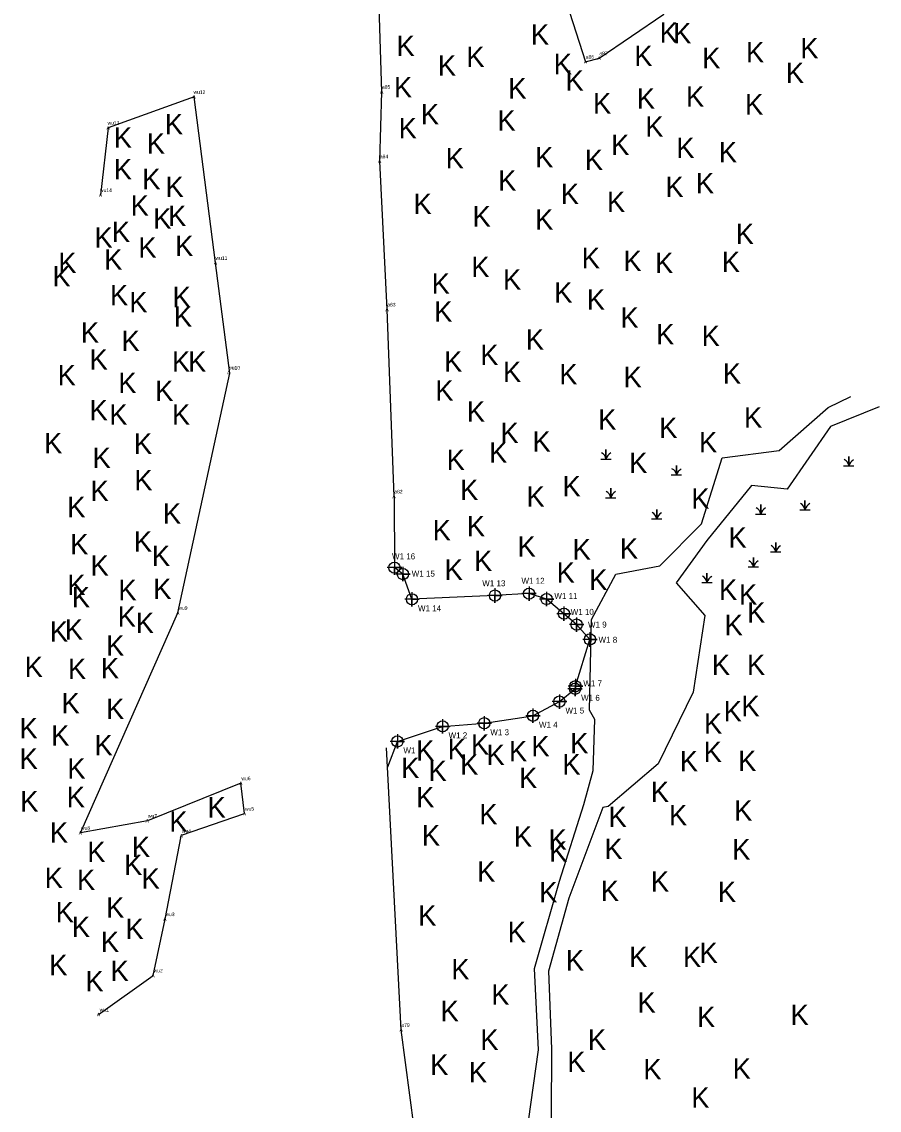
# Model space of a CAD drawing. Extents: x 2028512 to 2029541, y 737100 to 738747.
# Drawn here: x 2028728.5 to 2029086.2, y 737567.9 to 738021.9 of the extents above; entities that cross this region are included whole.
import ezdxf

# ---------------------------------------------------------------- set-up
doc = ezdxf.new("R2010")
doc.units = 0
for name, color, linetype in [('Exist Hydro Jurisdictional Stream or Body of Water NEU Mitigable', 7, 'Continuous'), ('Exist Hydro Swamp or Marsh', 7, 'Continuous'), ('Old_Level_10', 7, 'Continuous'), ('Old_Level_20', 7, 'Continuous'), ('Old_Level_52', 7, 'Continuous'), ('Old_Level_55', 7, 'Continuous'), ('Old_Level_61', 7, 'Continuous')]:
    doc.layers.add(name, color=color, linetype=linetype)

msp = doc.modelspace()

# ---------------------------------------------------------------- linework, layer by layer
at = {"layer": 'Exist Hydro Jurisdictional Stream or Body of Water NEU Mitigable'}
for points in [[(2028936, 737517.23), (2028942.42, 737539.85), (2028939.91, 737563.38), (2028944.05, 737593.1), (2028942.37, 737627.04), (2028952.81, 737663.43), (2028963.03, 737695.43), (2028966.79, 737709.62), (2028967.55, 737730.9), (2028965.32, 737734.83), (2028966.1, 737772.62), (2028976.38, 737791.55), (2028994.69, 737794.94), (2029012.11, 737812.51), (2029020.64, 737839.95), (2029044.47, 737843.01), (2029064.89, 737861), (2029074.27, 737865.65)], [(2029086.17, 737861.26), (2029065.82, 737853.05), (2029047.81, 737826.9), (2029032.96, 737828.41), (2029014.3, 737805.56), (2029001.47, 737787.92), (2029013.48, 737774.19), (2029008.57, 737742.32), (2028993.96, 737712.46), (2028973.16, 737694.62), (2028970.92, 737694.24), (2028956.66, 737656.32), (2028948.19, 737625.98), (2028949.49, 737593.57), (2028949.29, 737565.55), (2028947.28, 737538.25), (2028941.59, 737516.37), (2028941.83, 737507.52)]]:
    msp.add_lwpolyline(points, dxfattribs=at)
at = {"layer": 'Exist Hydro Swamp or Marsh'}
for p, q in [((2028972.2, 737841.29), (2028972.2, 737841.29)), ((2029073.47, 737838.42), (2029073.47, 737838.42)), ((2029001.59, 737834.65), (2029001.59, 737834.65)), ((2028974.17, 737825.15), (2028974.17, 737825.15)), ((2028993.35, 737816.36), (2028993.35, 737816.36)), ((2029036.73, 737818.34), (2029036.73, 737818.34)), ((2029055.19, 737820.13), (2029055.19, 737820.13)), ((2029043, 737802.55), (2029043, 737802.55)), ((2029033.68, 737796.28), (2029033.68, 737796.28)), ((2029014.32, 737789.82), (2029014.32, 737789.82))]:
    msp.add_line(p, q, dxfattribs=at)
for points in [[(2028970.05, 737839.51), (2028972.2, 737839.51), (2028972.2, 737843.45), (2028972.2, 737839.51), (2028974.35, 737839.51)], [(2029071.32, 737836.64), (2029073.47, 737836.64), (2029073.47, 737840.58), (2029073.47, 737836.64), (2029075.62, 737836.64)], [(2028999.44, 737832.87), (2029001.6, 737832.87), (2029001.6, 737836.82), (2029001.6, 737832.87), (2029003.75, 737832.87)], [(2028972.02, 737823.37), (2028974.17, 737823.37), (2028974.17, 737827.31), (2028974.17, 737823.37), (2028976.32, 737823.37)], [(2029034.58, 737816.55), (2029036.73, 737816.55), (2029036.73, 737820.5), (2029036.73, 737816.55), (2029038.88, 737816.55)], [(2029053.04, 737818.35), (2029055.19, 737818.35), (2029055.19, 737822.29), (2029055.19, 737818.35), (2029057.34, 737818.35)], [(2028991.2, 737814.58), (2028993.35, 737814.58), (2028993.35, 737818.53), (2028993.35, 737814.58), (2028995.5, 737814.58)], [(2029040.85, 737800.77), (2029043, 737800.77), (2029043, 737804.72), (2029043, 737800.77), (2029045.15, 737800.77)], [(2029031.53, 737794.49), (2029033.68, 737794.49), (2029033.68, 737798.44), (2029033.68, 737794.49), (2029035.83, 737794.49)], [(2029012.17, 737788.04), (2029014.32, 737788.04), (2029014.32, 737791.98), (2029014.32, 737788.04), (2029016.47, 737788.04)]]:
    msp.add_lwpolyline(points, dxfattribs=at)
for centre, radius, start, end in [((2028969.13, 737839.28), 3.07, 4.1403, 67.535), ((2028976.76, 737837.99), 4.81, 122.1274, 161.6222), ((2029070.41, 737836.42), 3.07, 4.1403, 67.535), ((2029078.03, 737835.12), 4.81, 122.1274, 161.6222), ((2028998.53, 737832.65), 3.07, 4.1403, 67.535), ((2029006.16, 737831.36), 4.81, 122.1274, 161.6222), ((2028971.1, 737823.15), 3.07, 4.1403, 67.535), ((2028978.73, 737821.85), 4.81, 122.1274, 161.6222), ((2029052.12, 737818.12), 3.07, 4.1403, 67.535), ((2029059.75, 737816.83), 4.81, 122.1274, 161.6222), ((2028990.28, 737814.36), 3.07, 4.1403, 67.535), ((2028997.91, 737813.06), 4.81, 122.1274, 161.6222), ((2029033.66, 737816.33), 3.07, 4.1403, 67.535), ((2029041.29, 737815.04), 4.81, 122.1274, 161.6222), ((2029039.93, 737800.55), 3.07, 4.1403, 67.535), ((2029047.56, 737799.26), 4.81, 122.1274, 161.6222), ((2029030.61, 737794.27), 3.07, 4.1403, 67.535), ((2029038.24, 737792.98), 4.81, 122.1274, 161.6222), ((2029011.26, 737787.82), 3.07, 4.1403, 67.535), ((2029018.88, 737786.52), 4.81, 122.1274, 161.6222)]:
    msp.add_arc(centre, radius, start, end, dxfattribs=at)
at = {"layer": 'Old_Level_20'}
for points in [[(2028883.99, 737797.22), (2028883.99, 737791.22), (2028883.99, 737794.22), (2028886.99, 737794.22), (2028880.99, 737794.22)], [(2028887.5, 737794.52), (2028887.5, 737788.52), (2028887.5, 737791.52), (2028890.5, 737791.52), (2028884.5, 737791.52)], [(2028891.28, 737784.02), (2028891.28, 737778.02), (2028891.28, 737781.02), (2028894.28, 737781.02), (2028888.28, 737781.02)], [(2028925.89, 737785.59), (2028925.89, 737779.59), (2028925.89, 737782.59), (2028928.89, 737782.59), (2028922.89, 737782.59)], [(2028940.12, 737786.37), (2028940.12, 737780.37), (2028940.12, 737783.37), (2028943.12, 737783.37), (2028937.12, 737783.37)], [(2028947.42, 737784.12), (2028947.42, 737778.12), (2028947.42, 737781.12), (2028950.42, 737781.12), (2028944.42, 737781.12)], [(2028954.66, 737778.02), (2028954.66, 737772.02), (2028954.66, 737775.02), (2028957.66, 737775.02), (2028951.66, 737775.02)], [(2028959.93, 737773.49), (2028959.93, 737767.49), (2028959.93, 737770.49), (2028962.93, 737770.49), (2028956.93, 737770.49)], [(2028965.52, 737767.25), (2028965.52, 737761.25), (2028965.52, 737764.25), (2028968.52, 737764.25), (2028962.52, 737764.25)], [(2028959.48, 737747.78), (2028959.48, 737741.78), (2028959.48, 737744.78), (2028962.48, 737744.78), (2028956.48, 737744.78)], [(2028959.33, 737746.68), (2028959.33, 737740.68), (2028959.33, 737743.68), (2028962.33, 737743.68), (2028956.33, 737743.68)], [(2028952.81, 737741.37), (2028952.81, 737735.37), (2028952.81, 737738.37), (2028955.81, 737738.37), (2028949.81, 737738.37)], [(2028941.75, 737735.44), (2028941.75, 737729.44), (2028941.75, 737732.44), (2028944.75, 737732.44), (2028938.75, 737732.44)], [(2028904.05, 737731.02), (2028904.05, 737725.02), (2028904.05, 737728.02), (2028907.05, 737728.02), (2028901.05, 737728.02)], [(2028921.45, 737732.32), (2028921.45, 737726.32), (2028921.45, 737729.32), (2028924.45, 737729.32), (2028918.45, 737729.32)], [(2028885.21, 737724.73), (2028885.21, 737718.73), (2028885.21, 737721.73), (2028888.21, 737721.73), (2028882.21, 737721.73)]]:
    msp.add_lwpolyline(points, dxfattribs=at)
for centre in [(2028883.99, 737794.22), (2028887.5, 737791.52), (2028925.89, 737782.59), (2028940.12, 737783.37), (2028891.28, 737781.02), (2028947.42, 737781.12), (2028954.66, 737775.02), (2028959.93, 737770.49), (2028965.52, 737764.25), (2028959.33, 737743.68), (2028959.48, 737744.78), (2028952.81, 737738.37), (2028941.75, 737732.44), (2028904.05, 737728.02), (2028921.45, 737729.32), (2028885.21, 737721.73)]:
    msp.add_circle(centre, 2.34, dxfattribs=at)
at = {"layer": 'Old_Level_52'}
for points in [[(2028878.7, 737992.71), (2028876.87, 738050.54), (2028924.08, 738056.04), (2028953.04, 738038.2), (2028963.71, 738005.21), (2028969.41, 738006.68), (2028996.29, 738025.08), (2028999.97, 738052.31), (2028981.59, 738072.49), (2028952.85, 738139.55), (2028963.08, 738144.58), (2028949.25, 738167.62)], [(2028883.86, 737823.92), (2028880.93, 737901.91), (2028877.85, 737963.73), (2028878.7, 737992.71)], [(2028877.65, 737963.94), (2028877.65, 737963.76), (2028877.65, 737963.76)], [(2028883.86, 737823.92), (2028883.99, 737794.22), (2028883.99, 737794.22)], [(2028885.21, 737721.73), (2028904.05, 737728.02), (2028921.45, 737729.32), (2028941.75, 737732.44), (2028952.81, 737738.37), (2028959.33, 737743.68), (2028959.48, 737744.78), (2028965.52, 737764.25), (2028959.93, 737770.49), (2028954.66, 737775.02), (2028947.42, 737781.12), (2028940.12, 737783.37), (2028925.89, 737782.59), (2028891.28, 737781.02), (2028887.5, 737791.52), (2028883.99, 737794.22)], [(2028881.21, 737711.19), (2028885.21, 737721.73), (2028884.23, 737721.63)], [(2028895.42, 737367.29), (2028901.12, 737382.42), (2028902.03, 737427.96), (2028897.22, 737471.61), (2028895.79, 737533.3), (2028886.82, 737601.44), (2028880.64, 737719.02)]]:
    msp.add_lwpolyline(points, dxfattribs=at)
at = {"layer": 'Old_Level_55'}
for points in [[(2028795.15, 737682.58), (2028821.46, 737691.61), (2028819.95, 737704.32), (2028780.94, 737688.66), (2028753.03, 737683.62), (2028793.67, 737775.38), (2028815.36, 737875.27), (2028809.37, 737921.33), (2028800.46, 737990.56), (2028764.62, 737977.67), (2028761.43, 737949.62)], [(2028760.58, 737607.83), (2028783.32, 737624.12), (2028788.28, 737647.62), (2028795.08, 737682.28)]]:
    msp.add_lwpolyline(points, dxfattribs=at)

# ---------------------------------------------------------------- texts
at = {"layer": 'Old_Level_10'}
for p in [(2028940.89, 738012.33), (2028994.6, 738013.11), (2029000.21, 738012.9), (2028884.85, 738007.59), (2028913.97, 738003.05), (2028984.03, 738003.4), (2029012.29, 738002.54), (2029030.62, 738004.91), (2029053.27, 738006.64), (2028902.1, 737999.39), (2028950.38, 738000.03), (2029047.23, 737996.36), (2028883.77, 737990.32), (2028931.44, 737989.89), (2028955.34, 737993.13), (2028985.07, 737985.67), (2029005.6, 737986.44), (2028966.77, 737983.63), (2029030.19, 737983.2), (2028894.98, 737979.1), (2028926.91, 737976.51), (2028788.21, 737974.98), (2028885.71, 737973.27), (2028988.6, 737973.92), (2028766.93, 737969.32), (2028780.67, 737966.89), (2028974.37, 737966.36), (2029001.55, 737965.07), (2029019.28, 737963.28), (2028905.34, 737960.75), (2028942.66, 737961.18), (2028963.37, 737960.11), (2028766.93, 737956.11), (2028778.78, 737952.07), (2028788.48, 737948.84), (2028927.23, 737951.46), (2028996.99, 737948.8), (2029009.72, 737950.31), (2028953.35, 737945.86), (2028773.93, 737941.02), (2028891.94, 737941.67), (2028972.62, 737942.54), (2028783.36, 737935.63), (2028789.56, 737936.71), (2028916.53, 737936.49), (2028942.64, 737935.2), (2028766.12, 737930.08), (2028758.85, 737927.65), (2029026.33, 737929.16), (2028777.17, 737923.5), (2028792.52, 737924.15), (2028743.76, 737917.14), (2028762.89, 737918.49), (2028962.06, 737919.12), (2028979.47, 737917.88), (2028992.68, 737917.07), (2029020.51, 737917.5), (2028916.04, 737915.39), (2028741.34, 737911.48), (2028899.49, 737908.44), (2028929.26, 737910.16), (2028765.31, 737903.66), (2028791.44, 737902.85), (2028950.62, 737904.77), (2028773.39, 737900.7), (2028964.21, 737901.75), (2028791.98, 737894.77), (2028900.57, 737896.78), (2028978.23, 737894.24), (2028753.19, 737888.03), (2028770.16, 737884.52), (2028938.75, 737885.13), (2028993.11, 737887.29), (2029012.09, 737886.64), (2028756.82, 737876.83), (2028791.17, 737875.9), (2028797.91, 737875.9), (2028904.67, 737875.96), (2028919.77, 737878.7), (2028929.26, 737871.64), (2029020.94, 737870.99), (2028743.49, 737870.24), (2028768.81, 737867), (2028952.73, 737870.61), (2028979.52, 737869.48), (2028784.19, 737863.77), (2028901, 737863.87), (2028756.82, 737855.68), (2028765.04, 737853.8), (2028791.17, 737853.8), (2028914.17, 737855.06), (2029029.78, 737852.65), (2028968.95, 737851.78), (2028994.41, 737848.33), (2028928.18, 737846.17), (2028737.83, 737841.94), (2028775.28, 737841.67), (2028941.54, 737842.62), (2029011.02, 737842.29), (2028758.07, 737835.78), (2028905.75, 737834.95), (2028923.44, 737837.97), (2028981.9, 737833.66), (2028775.48, 737826.45), (2028757.23, 737821.99), (2028911.36, 737822.43), (2028954.07, 737823.94), (2028939.05, 737819.61), (2029007.78, 737818.76), (2028747.49, 737815.26), (2028787.4, 737812.56), (2028914.17, 737807.32), (2028899.92, 737805.6), (2028748.74, 737799.71), (2028775.28, 737800.86), (2028935.3, 737798.84), (2029023.31, 737802.51), (2028782.82, 737794.93), (2028958.27, 737797.61), (2028978.01, 737797.98), (2028757.23, 737790.89), (2028904.89, 737789.13), (2028917.18, 737792.8), (2028951.64, 737787.91), (2028965.15, 737784.96), (2028747.53, 737782.8), (2028768.81, 737780.64), (2028783.36, 737781.18), (2029019.33, 737780.78), (2028749.42, 737777.68), (2029027.68, 737778.82), (2029031.08, 737771.22), (2028768.54, 737769.59), (2028776.09, 737766.9), (2028740.26, 737763.39), (2028746.46, 737764.2), (2029021.67, 737766.04), (2028763.7, 737757.46), (2028729.75, 737748.57), (2029016.38, 737749.46), (2029031, 737749.46), (2028747.8, 737747.76), (2028761.54, 737748.03), (2028745.11, 737733.48), (2028763.7, 737731.05), (2029021.3, 737730.05), (2029028.67, 737732.26), (2028727.6, 737722.96), (2029013.07, 737725.01), (2028740.8, 737720), (2028957.29, 737716.78), (2028758.85, 737715.96), (2028893.02, 737713.7), (2028906.19, 737714.32), (2028915.89, 737716.17), (2028922.4, 737711.87), (2028931.74, 737713.46), (2028941.08, 737715.55), (2029012.96, 737713.16), (2028727.6, 737710.3), (2028911.36, 737707.87), (2028953.97, 737707.93), (2029002.99, 737709.29), (2029027.32, 737709.41), (2028747.53, 737706.25), (2028886.78, 737706.46), (2028898.2, 737705.23), (2028935.95, 737702.26), (2028747.26, 737694.31), (2028893.02, 737694.28), (2028990.91, 737696.47), (2028727.87, 737692.51), (2028805.99, 737690), (2028919.38, 737687.14), (2028973.27, 737686.08), (2028998.5, 737686.72), (2029025.68, 737688.67), (2028790.1, 737684.07), (2028740.26, 737679.49), (2028895.39, 737678.31), (2028933.79, 737677.87), (2028948.24, 737676.58), (2028755.88, 737671.4), (2028774.47, 737673.56), (2028948.46, 737671.62), (2028971.54, 737672.7), (2029024.82, 737672.48), (2028771.24, 737666.01), (2028918.48, 737663.2), (2028738.1, 737660.62), (2028751.57, 737659.81), (2028778.51, 737660.35), (2028990.95, 737659.1), (2028944.36, 737654.57), (2028970.03, 737655.21), (2029018.89, 737654.8), (2028742.68, 737646.33), (2028763.7, 737648.22), (2028893.88, 737644.9), (2028749.42, 737640.14), (2028771.78, 737639.33), (2028931.2, 737638.01), (2028761.54, 737633.94), (2028955.46, 737626.19), (2028981.9, 737627.63), (2029004.33, 737627.63), (2029011.23, 737629.36), (2028739.99, 737624.23), (2028765.58, 737621.81), (2028907.69, 737622.45), (2028755.08, 737617.49), (2028924.36, 737611.89), (2028985.35, 737608.64), (2028903.21, 737605.05), (2029049.2, 737603.46), (2029010.19, 737602.56), (2028919.77, 737593.1), (2028964.64, 737593.1), (2028898.86, 737582.66), (2028956.08, 737583.9), (2028987.8, 737580.79), (2029025.04, 737581.01), (2028915.03, 737579.55), (2029007.78, 737568.93)]:
    msp.add_text('K', height=8.5, dxfattribs=at).set_placement(p)
at = {"layer": 'Old_Level_20'}
for p in [(2028968.66, 738005.93), (2028968.66, 738005.93), (2028968.66, 738005.93), (2028968.66, 738005.93), (2028962.96, 738004.46), (2028962.96, 738004.46), (2028962.96, 738004.46), (2028962.96, 738004.46), (2028877.95, 737991.96), (2028799.71, 737989.81), (2028763.87, 737976.92), (2028877.1, 737962.98), (2028760.68, 737948.87), (2028808.62, 737920.58), (2028880.18, 737901.16), (2028814.17, 737874.84), (2028883.11, 737823.17), (2028792.92, 737774.63), (2028819.2, 737703.57), (2028780.19, 737687.91), (2028820.71, 737690.86), (2028752.28, 737682.87), (2028794.38, 737681.61), (2028787.53, 737646.87), (2028782.57, 737623.37), (2028759.83, 737607.08), (2028886.07, 737600.69)]:
    msp.add_text('A', height=1.5, dxfattribs=at).set_placement(p)
at = {"layer": 'Old_Level_61'}
for s, height, p in [('a86', 1.5, (2028963.75, 738006.46)), ('a86', 1.5, (2028963.75, 738006.46)), ('a86', 1.5, (2028963.75, 738006.46)), ('a86', 1.5, (2028963.75, 738006.46)), ('a87', 1.5, (2028969.45, 738007.93)), ('a87', 1.5, (2028969.45, 738007.93)), ('a87', 1.5, (2028969.45, 738007.93)), ('a87', 1.5, (2028969.45, 738007.93)), ('wu12', 1.5, (2028800.17, 737991.81)), ('a85', 1.5, (2028878.75, 737993.96)), ('wu13', 1.5, (2028764.33, 737978.92)), ('a84', 1.5, (2028877.9, 737964.98)), ('wu14', 1.5, (2028761.14, 737950.87)), ('wu11', 1.5, (2028809.34, 737922.58)), ('a83', 1.5, (2028880.97, 737903.16)), ('wu10', 1.5, (2028814.63, 737876.84)), ('a82', 1.5, (2028883.91, 737825.17)), ('W1 16', 2.5, (2028882.95, 737797.68)), ('W1 15', 2.5, (2028891.17, 737790.48)), ('W1 13', 2.5, (2028920.58, 737786.47)), ('W1 12', 2.5, (2028936.95, 737787.47)), ('W1 11', 2.5, (2028950.67, 737781.15)), ('wu9', 1.5, (2028793.86, 737776.63)), ('W1 14', 2.5, (2028893.78, 737776.03)), ('W1 10', 2.5, (2028957.48, 737774.52)), ('W1 9', 2.5, (2028964.68, 737769.23)), ('W1 8', 2.5, (2028969.09, 737762.89)), ('W1 7', 2.5, (2028962.73, 737744.7)), ('W1 6', 2.5, (2028961.83, 737738.68)), ('W1 5', 2.5, (2028955.31, 737733.38)), ('W1 4', 2.5, (2028944.25, 737727.44)), ('W1 2', 2.5, (2028906.55, 737723.02)), ('W1 3', 2.5, (2028923.95, 737724.32)), ('W1 1', 2.5, (2028887.71, 737716.73)), ('wu6', 1.5, (2028820.15, 737705.57)), ('wu5', 1.5, (2028821.66, 737692.86)), ('wu7', 1.5, (2028781.14, 737689.91)), ('wu8', 1.5, (2028753.23, 737684.87)), ('wu4', 1.5, (2028795.33, 737683.61)), ('wu3', 1.5, (2028788.47, 737648.87)), ('wu2', 1.5, (2028783.52, 737625.37)), ('wu1', 1.5, (2028761.03, 737609.08)), ('a79', 1.5, (2028886.87, 737602.69))]:
    msp.add_text(s, height=height, dxfattribs=at).set_placement(p)

doc.saveas('drawing.dxf')
